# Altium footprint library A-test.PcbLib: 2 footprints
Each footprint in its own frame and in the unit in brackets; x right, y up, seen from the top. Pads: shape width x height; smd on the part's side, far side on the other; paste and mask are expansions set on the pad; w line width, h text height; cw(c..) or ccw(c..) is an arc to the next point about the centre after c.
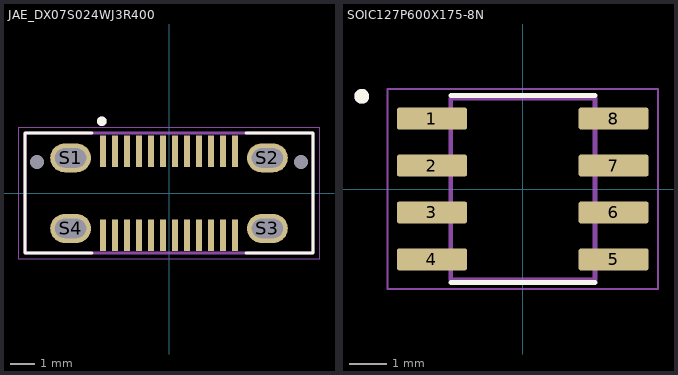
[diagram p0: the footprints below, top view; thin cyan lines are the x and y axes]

## JAE_DX07S024WJ3R400 [mm]
height 401.575
pads (30):
  rect 0.27x1.3 smd mask+0.103: A1(-2.75,1.75) A2(-2.25,1.75) A3(-1.75,1.75) A4(-1.25,1.75) A5(-0.75,1.75) A6(-0.25,1.75) A7(0.25,1.75) A8(0.75,1.75) A9(1.25,1.75) A10(1.75,1.75) A11(2.25,1.75) A12(2.75,1.75) B1(2.75,-1.75) B2(2.25,-1.75) B3(1.75,-1.75) B4(1.25,-1.75) B5(0.75,-1.75) B6(0.25,-1.75) B7(-0.25,-1.75) B8(-0.75,-1.75) B9(-1.25,-1.75) B10(-1.75,-1.75) B11(-2.25,-1.75) B12(-2.75,-1.75)
  round 0 hole 0.6 unplated: DRILL1(-5.5,1.3) DRILL2(5.5,1.3)
  oval 1.7x1.2 hole 0.8 slot 1.3 at 0 deg mask+0.1: S1(-4.1,1.47) S2(4.1,1.47) S3(4.1,-1.47) S4(-4.1,-1.47)
Top Overlay:
  circle w0.2: c-2.8,3 r0.1
  lines w0.127: -3.2,-2.5 -6,-2.5 -6,2.5 -3.2,2.5 ; 3.2,-2.5 6,-2.5 6,2.5 3.2,2.5
Mechanical 15:
  circle w0.2: c-2.8,3 r0.1
  lines w0.127: -6,-2.5 6,-2.5 6,2.5 -6,2.5 -6,-2.5
Drill Drawing:
  lines w0.001: -4.35,-1.07 -3.85,-1.07 cw(c-3.85,-1.47) -3.45,-1.47 cw(c-3.85,-1.47) -3.85,-1.87 -4.35,-1.87 cw(c-4.35,-1.47) -4.75,-1.47 cw(c-4.35,-1.47) -4.35,-1.07 ; -4.35,1.87 -3.85,1.87 cw(c-3.85,1.47) -3.45,1.47 cw(c-3.85,1.47) -3.85,1.07 -4.35,1.07 cw(c-4.35,1.47) -4.75,1.47 cw(c-4.35,1.47) -4.35,1.87 ; 4.35,-1.07 3.85,-1.07 ccw(c3.85,-1.47) 3.45,-1.47 ccw(c3.85,-1.47) 3.85,-1.87 4.35,-1.87 ccw(c4.35,-1.47) 4.75,-1.47 ccw(c4.35,-1.47) 4.35,-1.07 ; 4.35,1.87 3.85,1.87 ccw(c3.85,1.47) 3.45,1.47 ccw(c3.85,1.47) 3.85,1.07 4.35,1.07 ccw(c4.35,1.47) 4.75,1.47 ccw(c4.35,1.47) 4.35,1.87
Mechanical 20:
  lines w0.05: -6.25,-2.75 6.25,-2.75 6.25,2.75 -6.25,2.75 -6.25,-2.75

## SOIC127P600X175-8N [mm]
pads (8):
  rrect25% 1.9x0.6 smd mask+0.103: 1(-2.455,1.905) 2(-2.455,0.635) 3(-2.455,-0.635) 4(-2.455,-1.905) 5(2.455,-1.905) 6(2.455,-0.635) 7(2.455,0.635) 8(2.455,1.905)
Top Overlay:
  circle w0.2: c-4.355,2.505 r0.1
  lines w0.127: -1.95,-2.525 1.95,-2.525 ; -1.95,2.525 1.95,2.525
Mechanical 15:
  circle w0.2: c-4.355,2.505 r0.1
  lines w0.127: -1.95,-2.45 1.95,-2.45 1.95,2.45 -1.95,2.45 -1.95,-2.45
Mechanical 20:
  lines w0.05: -3.655,-2.7 3.655,-2.7 3.655,2.7 -3.655,2.7 -3.655,-2.7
